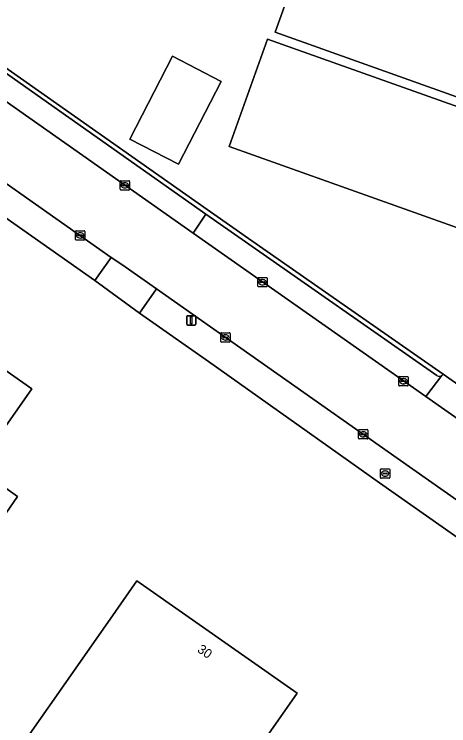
# Model space of a CAD drawing. Extents: x 155018 to 156648, y 383979 to 385733.
# Drawn here: x 155561.5 to 155608.1, y 384875.8 to 384952 of the extents above; entities that cross this region are included whole.
import ezdxf

# ---------------------------------------------------------------- set-up
doc = ezdxf.new("R2010")
doc.units = 0
for name, color, linetype in [('IMGEO_Brandkraan', 7, 'Continuous'), ('IMGEO_Erf', 7, 'Continuous'), ('IMGEO_Kolk', 7, 'Continuous'), ('IMGEO_Lichtmast', 7, 'Continuous'), ('IMGEO_Pand', 7, 'Continuous'), ('IMGEO_Pand_nummerreeks', 7, 'Continuous'), ('IMGEO_Parkeervlak_open', 7, 'Continuous'), ('IMGEO_Rijbaan_lokaal_gesloten', 7, 'Continuous'), ('IMGEO_Voetpad_open', 7, 'Continuous')]:
    doc.layers.add(name, color=color, linetype=linetype)

msp = doc.modelspace()

# ---------------------------------------------------------------- linework, layer by layer
at = {"layer": 'IMGEO_Brandkraan'}
for p, q in [((155600.733, 384902.367), (155600.733, 384903.219)), ((155600.808, 384903.293), (155601.66, 384903.293)), ((155600.992, 384902.787), (155600.992, 384902.799)), ((155601.43, 384902.75), (155601.032, 384902.75)), ((155601.035, 384902.836), (155601.433, 384902.836)), ((155601.221, 384903.073), (155601.246, 384903.073)), ((155601.476, 384902.799), (155601.476, 384902.787)), ((155601.734, 384903.219), (155601.734, 384902.367)), ((155601.66, 384902.293), (155600.808, 384902.293)), ((155601.244, 384902.513), (155601.219, 384902.513))]:
    msp.add_line(p, q, dxfattribs=at)
for points in [[(155600.733, 384902.367), (155600.733, 384903.219)], [(155600.808, 384903.293), (155601.66, 384903.293)], [(155601.734, 384903.219), (155601.734, 384902.367)], [(155601.66, 384902.293), (155600.808, 384902.293)]]:
    msp.add_lwpolyline(points, dxfattribs=at)
for centre, radius, start, end in [((155600.81, 384903.217), 0.0765, 91.55205, 178.44795), ((155600.81, 384903.217), 0.0765, 91.55205, 178.44795), ((155601.032, 384902.796), 0.0403, 85.87752, 175.75265), ((155601.029, 384902.786), 0.0366, 178.93798, 274.71019), ((155601.433, 384902.793), 0.043, 264.86636, 352.45326), ((155601.437, 384902.798), 0.0386, 1.73085, 96.63898), ((155601.658, 384903.217), 0.0765, 1.55205, 88.44795), ((155601.658, 384903.217), 0.0765, 1.55205, 88.44795), ((155600.81, 384902.369), 0.0765, 181.55205, 268.44795), ((155600.81, 384902.369), 0.0765, 181.55205, 268.44795), ((155601.658, 384902.369), 0.0765, 271.55205, 358.44795), ((155601.658, 384902.369), 0.0765, 271.55205, 358.44795)]:
    msp.add_arc(centre, radius, start, end, dxfattribs=at)
for centre, major_axis, ratio, start_param, end_param in [((155601.22, 384902.793), (-0.387, 0.002), 0.722429, 4.712389, 7.853982), ((155601.245, 384902.793), (-0.39, 0.002), 0.717154, 1.570796, 4.712389)]:
    msp.add_ellipse(centre, major_axis=major_axis, ratio=ratio, start_param=start_param, end_param=end_param, dxfattribs=at)
at = {"layer": 'IMGEO_Erf'}
for points in [[(155663.21, 384917.49), (155630.178, 384929.273), (155625.14, 384931.07), (155632.162, 384950.755), (155623.212, 384953.942), (155618.1, 384939.84), (155589.46, 384950.07), (155591.136, 384954.781), (155607.234, 385000), (155633.333, 385073.311)], [(155457.525, 385018.63), (155458.619, 385017.864), (155484.145, 385000), (155491.64, 384994.721), (155500, 384988.865), (155510.83, 384981.203), (155511.294, 384981.88), (155516.258, 384978.35), (155515.775, 384977.663), (155553.601, 384951.142), (155553.738, 384951.046), (155554.058, 384951.47), (155560.497, 384946.89), (155560.229, 384946.497), (155580.857, 384931.994), (155586.597, 384927.958), (155607.46, 384913.427), (155617.317, 384906.512), (155620.874, 384904.014), (155651.48, 384882.509)], [(155645.703, 384870.176), (155613.715, 384892.628), (155600.657, 384901.793), (155582.308, 384914.778), (155574.917, 384919.981), (155570.133, 384923.483), (155539.854, 384944.743), (155535.161, 384948.038), (155534.984, 384948.163), (155531.101, 384950.889), (155530.5, 384951.311), (155510.828, 384965.124), (155506.264, 384968.328), (155505.588, 384968.803), (155501.395, 384971.747), (155500, 384972.727), (155492.047, 384978.311), (155491.266, 384978.86), (155482.605, 384984.76), (155482.381, 384984.92), (155460.927, 385000), (155450.653, 385007.222)], [(155543.877, 384924.937), (155545.004, 384924.158), (155545.287, 384924.561), (155563.372, 384911.879), (155557.442, 384903.43), (155561.847, 384900.331), (155558.976, 384896.238), (155532.714, 384858.794), (155540.579, 384853.259), (155545.535, 384849.771), (155571.761, 384887.2), (155574.63, 384891.294), (155591.828, 384879.262), (155575.198, 384855.542), (155560.868, 384835.103), (155560.52, 384834.638), (155543.355, 384846.66), (155543.923, 384847.471), (155538.96, 384850.949), (155531.075, 384856.475), (155530.489, 384855.639), (155507.887, 384871.48), (155500, 384877.008)]]:
    msp.add_lwpolyline(points, dxfattribs=at)
for points in [[(155614.592, 384931.262), (155613.208, 384927.617), (155584.535, 384937.812), (155588.645, 384949.317), (155617.291, 384939.126)], [(155579.102, 384935.924), (155573.878, 384938.612), (155578.46, 384947.479), (155583.664, 384944.79)]]:
    msp.add_lwpolyline(points, close=True, dxfattribs=at)
at = {"layer": 'IMGEO_Kolk'}
for p, q in [((155572.856, 384933.232), (155572.856, 384934.084)), ((155572.931, 384934.158), (155573.783, 384934.158)), ((155573.857, 384934.084), (155573.857, 384933.232)), ((155573.115, 384933.652), (155573.115, 384933.664)), ((155573.553, 384933.615), (155573.155, 384933.615)), ((155573.158, 384933.701), (155573.556, 384933.701)), ((155573.367, 384933.378), (155573.342, 384933.378)), ((155573.344, 384933.938), (155573.369, 384933.938)), ((155573.599, 384933.664), (155573.599, 384933.652)), ((155573.783, 384933.158), (155572.931, 384933.158)), ((155568.065, 384927.872), (155568.065, 384928.724)), ((155568.14, 384928.798), (155568.992, 384928.798)), ((155569.066, 384928.724), (155569.066, 384927.872)), ((155568.324, 384928.292), (155568.324, 384928.304)), ((155568.762, 384928.255), (155568.364, 384928.255)), ((155568.367, 384928.341), (155568.765, 384928.341)), ((155568.576, 384928.018), (155568.551, 384928.018)), ((155568.553, 384928.578), (155568.578, 384928.578)), ((155568.808, 384928.304), (155568.808, 384928.292)), ((155568.992, 384927.798), (155568.14, 384927.798)), ((155587.6, 384922.861), (155587.6, 384923.713)), ((155587.675, 384923.787), (155588.527, 384923.787)), ((155587.902, 384923.33), (155588.3, 384923.33)), ((155588.088, 384923.567), (155588.113, 384923.567)), ((155588.601, 384923.713), (155588.601, 384922.861)), ((155588.527, 384922.787), (155587.675, 384922.787)), ((155587.859, 384923.281), (155587.859, 384923.293)), ((155588.297, 384923.244), (155587.899, 384923.244)), ((155588.111, 384923.007), (155588.086, 384923.007)), ((155588.343, 384923.293), (155588.343, 384923.281)), ((155583.621, 384916.948), (155583.621, 384917.8)), ((155583.696, 384917.874), (155584.548, 384917.874)), ((155583.88, 384917.368), (155583.88, 384917.38)), ((155584.318, 384917.331), (155583.92, 384917.331)), ((155583.923, 384917.417), (155584.321, 384917.417)), ((155584.109, 384917.654), (155584.134, 384917.654)), ((155584.364, 384917.38), (155584.364, 384917.368)), ((155584.622, 384917.8), (155584.622, 384916.948)), ((155584.548, 384916.874), (155583.696, 384916.874)), ((155584.132, 384917.094), (155584.107, 384917.094)), ((155602.702, 384912.253), (155602.702, 384913.105)), ((155602.777, 384913.179), (155603.629, 384913.179)), ((155602.961, 384912.673), (155602.961, 384912.685)), ((155603.004, 384912.722), (155603.402, 384912.722)), ((155603.19, 384912.959), (155603.215, 384912.959)), ((155603.445, 384912.685), (155603.445, 384912.673)), ((155603.703, 384913.105), (155603.703, 384912.253)), ((155603.629, 384912.179), (155602.777, 384912.179)), ((155603.399, 384912.636), (155603.001, 384912.636)), ((155603.213, 384912.399), (155603.188, 384912.399)), ((155598.401, 384906.57), (155598.401, 384907.422)), ((155598.476, 384907.496), (155599.328, 384907.496)), ((155599.402, 384907.422), (155599.402, 384906.57)), ((155598.66, 384906.99), (155598.66, 384907.002)), ((155599.098, 384906.953), (155598.7, 384906.953)), ((155598.703, 384907.039), (155599.101, 384907.039)), ((155598.912, 384906.716), (155598.887, 384906.716)), ((155598.889, 384907.276), (155598.914, 384907.276)), ((155599.144, 384907.002), (155599.144, 384906.99)), ((155599.328, 384906.496), (155598.476, 384906.496))]:
    msp.add_line(p, q, dxfattribs=at)
for points in [[(155572.856, 384933.232), (155572.856, 384934.084)], [(155572.931, 384934.158), (155573.783, 384934.158)], [(155573.857, 384934.084), (155573.857, 384933.232)], [(155573.783, 384933.158), (155572.931, 384933.158)], [(155568.065, 384927.872), (155568.065, 384928.724)], [(155568.14, 384928.798), (155568.992, 384928.798)], [(155569.066, 384928.724), (155569.066, 384927.872)], [(155568.992, 384927.798), (155568.14, 384927.798)], [(155587.6, 384922.861), (155587.6, 384923.713)], [(155587.675, 384923.787), (155588.527, 384923.787)], [(155588.601, 384923.713), (155588.601, 384922.861)], [(155588.527, 384922.787), (155587.675, 384922.787)], [(155583.621, 384916.948), (155583.621, 384917.8)], [(155583.696, 384917.874), (155584.548, 384917.874)], [(155584.622, 384917.8), (155584.622, 384916.948)], [(155584.548, 384916.874), (155583.696, 384916.874)], [(155602.702, 384912.253), (155602.702, 384913.105)], [(155602.777, 384913.179), (155603.629, 384913.179)], [(155603.703, 384913.105), (155603.703, 384912.253)], [(155603.629, 384912.179), (155602.777, 384912.179)], [(155598.401, 384906.57), (155598.401, 384907.422)], [(155598.476, 384907.496), (155599.328, 384907.496)], [(155599.402, 384907.422), (155599.402, 384906.57)], [(155599.328, 384906.496), (155598.476, 384906.496)]]:
    msp.add_lwpolyline(points, dxfattribs=at)
for centre, radius, start, end in [((155572.933, 384934.082), 0.0765, 91.55205, 178.44795), ((155572.933, 384934.082), 0.0765, 91.55205, 178.44795), ((155573.781, 384934.082), 0.0765, 1.55205, 88.44795), ((155573.781, 384934.082), 0.0765, 1.55205, 88.44795), ((155572.933, 384933.234), 0.0765, 181.55205, 268.44795), ((155572.933, 384933.234), 0.0765, 181.55205, 268.44795), ((155573.155, 384933.661), 0.0403, 85.87752, 175.75265), ((155573.152, 384933.651), 0.0366, 178.93798, 274.71019), ((155573.556, 384933.658), 0.043, 264.86636, 352.45326), ((155573.56, 384933.663), 0.0386, 1.73085, 96.63898), ((155573.781, 384933.234), 0.0765, 271.55205, 358.44795), ((155573.781, 384933.234), 0.0765, 271.55205, 358.44795), ((155568.142, 384928.722), 0.0765, 91.55205, 178.44795), ((155568.142, 384928.722), 0.0765, 91.55205, 178.44795), ((155568.99, 384928.722), 0.0765, 1.55205, 88.44795), ((155568.99, 384928.722), 0.0765, 1.55205, 88.44795), ((155568.364, 384928.301), 0.0403, 85.87752, 175.75265), ((155568.361, 384928.291), 0.0366, 178.93798, 274.71019), ((155568.765, 384928.298), 0.043, 264.86636, 352.45326), ((155568.769, 384928.303), 0.0386, 1.73085, 96.63898), ((155568.142, 384927.874), 0.0765, 181.55205, 268.44795), ((155568.142, 384927.874), 0.0765, 181.55205, 268.44795), ((155568.99, 384927.874), 0.0765, 271.55205, 358.44795), ((155568.99, 384927.874), 0.0765, 271.55205, 358.44795), ((155587.677, 384923.711), 0.0765, 91.55205, 178.44795), ((155587.677, 384923.711), 0.0765, 91.55205, 178.44795), ((155587.899, 384923.29), 0.0403, 85.87752, 175.75265), ((155588.304, 384923.292), 0.0386, 1.73085, 96.63898), ((155588.525, 384923.711), 0.0765, 1.55205, 88.44795), ((155588.525, 384923.711), 0.0765, 1.55205, 88.44795), ((155587.677, 384922.863), 0.0765, 181.55205, 268.44795), ((155587.677, 384922.863), 0.0765, 181.55205, 268.44795), ((155587.896, 384923.28), 0.0366, 178.93798, 274.71019), ((155588.3, 384923.287), 0.043, 264.86636, 352.45326), ((155588.525, 384922.863), 0.0765, 271.55205, 358.44795), ((155588.525, 384922.863), 0.0765, 271.55205, 358.44795), ((155583.698, 384917.798), 0.0765, 91.55205, 178.44795), ((155583.698, 384917.798), 0.0765, 91.55205, 178.44795), ((155583.92, 384917.377), 0.0403, 85.87752, 175.75265), ((155583.917, 384917.367), 0.0366, 178.93798, 274.71019), ((155584.321, 384917.374), 0.043, 264.86636, 352.45326), ((155584.325, 384917.379), 0.0386, 1.73085, 96.63898), ((155584.546, 384917.798), 0.0765, 1.55205, 88.44795), ((155584.546, 384917.798), 0.0765, 1.55205, 88.44795), ((155583.698, 384916.95), 0.0765, 181.55205, 268.44795), ((155583.698, 384916.95), 0.0765, 181.55205, 268.44795), ((155584.546, 384916.95), 0.0765, 271.55205, 358.44795), ((155584.546, 384916.95), 0.0765, 271.55205, 358.44795), ((155602.779, 384913.103), 0.0765, 91.55205, 178.44795), ((155602.779, 384913.103), 0.0765, 91.55205, 178.44795), ((155603.001, 384912.682), 0.0403, 85.87752, 175.75265), ((155602.998, 384912.672), 0.0366, 178.93798, 274.71019), ((155603.402, 384912.679), 0.043, 264.86636, 352.45326), ((155603.406, 384912.684), 0.0386, 1.73085, 96.63898), ((155603.627, 384913.103), 0.0765, 1.55205, 88.44795), ((155603.627, 384913.103), 0.0765, 1.55205, 88.44795), ((155602.779, 384912.255), 0.0765, 181.55205, 268.44795), ((155602.779, 384912.255), 0.0765, 181.55205, 268.44795), ((155603.627, 384912.255), 0.0765, 271.55205, 358.44795), ((155603.627, 384912.255), 0.0765, 271.55205, 358.44795), ((155598.478, 384907.42), 0.0765, 91.55205, 178.44795), ((155598.478, 384907.42), 0.0765, 91.55205, 178.44795), ((155599.326, 384907.42), 0.0765, 1.55205, 88.44795), ((155599.326, 384907.42), 0.0765, 1.55205, 88.44795), ((155598.478, 384906.572), 0.0765, 181.55205, 268.44795), ((155598.478, 384906.572), 0.0765, 181.55205, 268.44795), ((155598.7, 384906.999), 0.0403, 85.87752, 175.75265), ((155598.697, 384906.989), 0.0366, 178.93798, 274.71019), ((155599.101, 384906.996), 0.043, 264.86636, 352.45326), ((155599.105, 384907.001), 0.0386, 1.73085, 96.63898), ((155599.326, 384906.572), 0.0765, 271.55205, 358.44795), ((155599.326, 384906.572), 0.0765, 271.55205, 358.44795)]:
    msp.add_arc(centre, radius, start, end, dxfattribs=at)
for centre, major_axis, ratio, start_param, end_param in [((155573.343, 384933.658), (-0.387, 0.002), 0.722429, 4.712389, 7.853982), ((155573.368, 384933.658), (-0.39, 0.002), 0.717154, 1.570796, 4.712389), ((155568.552, 384928.298), (-0.387, 0.002), 0.722429, 4.712389, 7.853982), ((155568.577, 384928.298), (-0.39, 0.002), 0.717154, 1.570796, 4.712389), ((155588.087, 384923.287), (-0.387, 0.002), 0.722429, 4.712389, 7.853982), ((155588.112, 384923.287), (-0.39, 0.002), 0.717154, 1.570796, 4.712389), ((155584.108, 384917.374), (-0.387, 0.002), 0.722429, 4.712389, 7.853982), ((155584.133, 384917.374), (-0.39, 0.002), 0.717154, 1.570796, 4.712389), ((155603.189, 384912.679), (-0.387, 0.002), 0.722429, 4.712389, 7.853982), ((155603.214, 384912.679), (-0.39, 0.002), 0.717154, 1.570796, 4.712389), ((155598.888, 384906.996), (-0.387, 0.002), 0.722429, 4.712389, 7.853982), ((155598.913, 384906.996), (-0.39, 0.002), 0.717154, 1.570796, 4.712389)]:
    msp.add_ellipse(centre, major_axis=major_axis, ratio=ratio, start_param=start_param, end_param=end_param, dxfattribs=at)
at = {"layer": 'IMGEO_Lichtmast'}
for p, q in [((155579.977, 384918.796), (155579.977, 384919.596)), ((155579.977, 384919.596), (155579.977, 384918.796)), ((155580.077, 384919.696), (155580.867, 384919.696)), ((155580.867, 384919.696), (155580.077, 384919.696)), ((155580.967, 384919.596), (155580.967, 384918.796)), ((155580.967, 384918.796), (155580.967, 384919.596)), ((155580.867, 384918.696), (155580.077, 384918.696)), ((155580.077, 384918.696), (155580.867, 384918.696))]:
    msp.add_line(p, q, dxfattribs=at)
msp.add_lwpolyline([(155580.397, 384919.571), (155580.547, 384919.571), (155580.547, 384918.821), (155580.397, 384918.821), (155580.397, 384919.571)], dxfattribs=at)
for centre, start, end in [((155580.077, 384919.596), 90, 180), ((155580.077, 384919.596), 90, 180), ((155580.867, 384919.596), 0, 90), ((155580.867, 384919.596), 360, 90), ((155580.077, 384918.796), 180, 270), ((155580.077, 384918.796), 180, 270), ((155580.867, 384918.796), 270, 0), ((155580.867, 384918.796), 270, 0)]:
    msp.add_arc(centre, 0.1, start, end, dxfattribs=at)
at = {"layer": 'IMGEO_Pand'}
for points in [[(155633.333, 385073.311), (155607.234, 385000), (155591.136, 384954.781), (155589.46, 384950.07), (155618.1, 384939.84), (155623.212, 384953.942), (155632.162, 384950.755), (155625.14, 384931.07), (155630.178, 384929.273), (155663.21, 384917.49)], [(155541.878, 384926.35), (155540.987, 384926.985), (155541.289, 384927.418), (155541.136, 384927.524), (155527.474, 384937.038), (155521.497, 384928.598), (155517.232, 384931.679), (155514.306, 384927.626), (155500, 384907.81), (155485.234, 384887.357), (155500, 384877.008), (155507.887, 384871.48), (155530.489, 384855.639), (155531.075, 384856.475), (155538.96, 384850.949), (155540.579, 384853.259), (155532.714, 384858.794), (155558.976, 384896.238), (155561.847, 384900.331), (155557.442, 384903.43), (155563.372, 384911.879), (155545.287, 384924.561), (155545.004, 384924.158), (155543.877, 384924.937)]]:
    msp.add_lwpolyline(points, dxfattribs=at)
for points in [[(155617.291, 384939.126), (155588.645, 384949.317), (155584.535, 384937.812), (155613.208, 384927.617), (155614.592, 384931.262)], [(155579.102, 384935.924), (155583.664, 384944.79), (155578.46, 384947.479), (155573.878, 384938.612)], [(155591.828, 384879.262), (155574.63, 384891.294), (155571.761, 384887.2), (155545.535, 384849.771), (155540.579, 384853.259), (155538.96, 384850.949), (155543.923, 384847.471), (155543.355, 384846.66), (155560.52, 384834.638), (155560.868, 384835.103), (155575.198, 384855.542)]]:
    msp.add_lwpolyline(points, close=True, dxfattribs=at)
at = {"layer": 'IMGEO_Parkeervlak_open'}
for points in [[(155560.072, 384946.265), (155558.57, 384944.057), (155580.666, 384928.528), (155582.038, 384930.579), (155560.322, 384945.869)], [(155606.786, 384913.278), (155586.27, 384927.599), (155582.038, 384930.579), (155580.666, 384928.528), (155605.603, 384911.034), (155607.302, 384913.282)]]:
    msp.add_lwpolyline(points, dxfattribs=at)
msp.add_lwpolyline([(155607.46, 384913.427), (155607.302, 384913.282), (155605.603, 384911.034), (155615.524, 384904.073), (155617.317, 384906.512)], close=True, dxfattribs=at)
msp.add_arc((155607.041, 384913.728), 0.517, 240.49681, 300.39148, dxfattribs=at)
at = {"layer": 'IMGEO_Rijbaan_lokaal_gesloten'}
for points in [[(155650.099, 384879.818), (155615.524, 384904.073), (155605.603, 384911.034), (155580.666, 384928.528), (155558.57, 384944.057), (155551.965, 384948.699), (155514.295, 384975.174), (155514.115, 384975.3), (155509.167, 384978.777), (155500, 384985.217), (155489.982, 384992.256), (155489.845, 384992.352), (155482.635, 384997.401), (155478.917, 385000), (155456.1, 385015.949)], [(155452.478, 385009.864), (155466.537, 385000), (155468.855, 384998.374), (155481.303, 384989.599), (155484.226, 384987.538), (155493.798, 384980.798), (155500, 384976.456), (155502.879, 384974.44), (155503.149, 384974.25), (155507.358, 384971.292), (155508.017, 384970.829), (155512.594, 384967.613), (155532.25, 384953.8), (155532.882, 384953.356), (155536.732, 384950.651), (155536.91, 384950.526), (155541.6, 384947.23), (155571.894, 384925.942), (155573.015, 384925.172), (155576.741, 384922.577), (155602.522, 384904.454), (155615.591, 384895.277), (155647.55, 384872.837)]]:
    msp.add_lwpolyline(points, dxfattribs=at)
at = {"layer": 'IMGEO_Voetpad_open'}
for points in [[(155541.6, 384947.23), (155536.91, 384950.526), (155535.161, 384948.038), (155539.854, 384944.743), (155570.133, 384923.483), (155571.894, 384925.942)], [(155574.917, 384919.981), (155576.741, 384922.577), (155573.015, 384925.172), (155571.894, 384925.942), (155570.133, 384923.483)], [(155615.591, 384895.277), (155602.522, 384904.454), (155576.741, 384922.577), (155574.917, 384919.981), (155582.308, 384914.778), (155600.657, 384901.793), (155613.715, 384892.628), (155645.703, 384870.176), (155647.55, 384872.837)]]:
    msp.add_lwpolyline(points, close=True, dxfattribs=at)
for points in [[(155607.302, 384913.282), (155607.46, 384913.427), (155586.597, 384927.958), (155580.857, 384931.994), (155560.229, 384946.497), (155560.072, 384946.265)], [(155560.322, 384945.869), (155582.038, 384930.579), (155586.27, 384927.599), (155606.786, 384913.278)]]:
    msp.add_lwpolyline(points, dxfattribs=at)
msp.add_arc((155607.041, 384913.728), 0.517, 240.49681, 300.39148, dxfattribs=at)

# ---------------------------------------------------------------- texts
at = {"layer": 'IMGEO_Pand_nummerreeks'}
msp.add_text('30', height=1, rotation=325.02093, dxfattribs=at).set_placement((155581.037, 384883.76))

doc.saveas('drawing.dxf')
